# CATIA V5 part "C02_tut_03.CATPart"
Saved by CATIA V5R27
Part number: Part1
Bounding box of the stored display mesh (mm): x 0 to 0, y -40 to 40, z -30 to 30
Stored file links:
  E:\_Deepak\2017_Deepak\CATIA\Resources\Tutorial Files\Tutorials\c02_catia_v5_6r2016_tut\C02_tut_03.CATPart
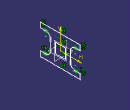
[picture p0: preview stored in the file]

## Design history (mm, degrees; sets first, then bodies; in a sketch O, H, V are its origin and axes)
Body1 (main body)
  Sketch1 on yz-plane, origin (0, 0, 0), H (0, 1, 0), V (0, 0, 1)
    line L1 (-40, -30) -> (40, -30)
    line L2 (40, -30) -> (40, -20)
    line L3 (40, -20) -> (30, -20)
    arc A1 centre (30, -10) radius 10 from (30, -20) to (20, -10) cw
    line L4 (20, -10) -> (20, 10)
    arc A2 centre (30, 10) radius 10 from (20, 10) to (30, 20) cw
    line L5 (30, 20) -> (40, 20)
    point P10 (40, 20)
    line L6 (40, 20) -> (40, 30)
    line L7 (40, 30) -> (-40, 30)
    line L8 (-40, 30) -> (-40, 20)
    point P13 (-40, 20)
    line L9 (-40, 20) -> (-30, 20)
    arc A3 centre (-30, 10) radius 10 from (-30, 20) to (-20, 10) cw
    line L10 (-20, 10) -> (-20, -10)
    arc A4 centre (-30, -10) radius 10 from (-20, -10) to (-30, -20) cw
    point P19 (-30, -20)
    line L11 (-30, -20) -> (-40, -20)
    point P20 (-40, -20)
    line L12 (-40, -20) -> (-40, -30)
    line L13 (-10, 10) -> (10, 10)
    line L14 (10, 10) -> (10, -10)
    line L15 (10, -10) -> (-10, -10)
    line L16 (-10, -10) -> (-10, 10)
    horizontal: L1 H, L3 H, L7 H, L13 H, L15 H
    vertical: L2 V, L6 V, L8 V, L14 V, L16 V
    tangency: A1 L3, L4 A1, A2 L4, L5 A2, L9 A2, A3 L9, L10 A3, A4 L10, L11 A4
    coincidence: P10 L2, P13 L5, P19 L3, P20 L8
